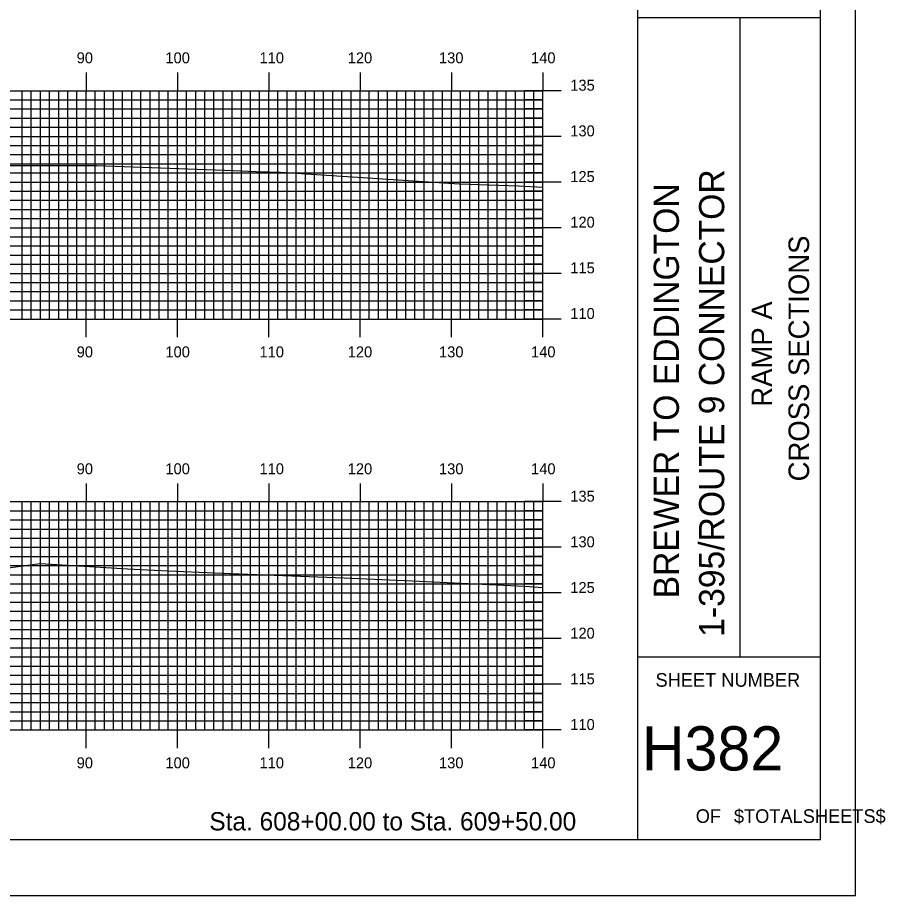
# Model space of a CAD drawing. Extents: x 842962 to 843305, y 363538 to 363758.
# Drawn here: x 843210.4 to 843305.4, y 363537.6 to 363633.7 of the extents above; entities that cross this region are included whole.
import ezdxf

# ---------------------------------------------------------------- set-up
doc = ezdxf.new("R2010")
doc.units = 0
for name, color, linetype in [('BORDER', 7, 'Continuous'), ('H_V ANNOTATION', 7, 'Continuous'), ('MAJOR', 7, 'Continuous'), ('MINOR', 7, 'Continuous'), ('PLOT BOUNDARY', 7, 'Continuous'), ('S_Roadway_Centerline', 7, 'Continuous')]:
    doc.layers.add(name, color=color, linetype=linetype)

msp = doc.modelspace()

# ---------------------------------------------------------------- linework, layer by layer
at = {"layer": 'BORDER'}
for p, q in [((843278.311, 363543.721), (843278.311, 363753.721)), ((843278.311, 363633.727), (843298.311, 363633.727)), ((843289.493, 363563.727), (843289.493, 363633.727)), ((843278.311, 363563.727), (843298.311, 363563.727))]:
    msp.add_line(p, q, dxfattribs=at)
msp.add_lwpolyline([(842978.311, 363543.721), (843298.311, 363543.721), (843298.311, 363753.721), (842978.311, 363753.721)], close=True, dxfattribs=at)
at = {"layer": 'MAJOR'}
for p, q in [((843217.911, 363627.725), (843217.911, 363625.721)), ((843227.911, 363627.725), (843227.911, 363625.721)), ((843237.911, 363627.725), (843237.911, 363625.721)), ((843247.911, 363627.725), (843247.911, 363625.721)), ((843257.911, 363627.725), (843257.911, 363625.721)), ((843267.911, 363627.725), (843267.911, 363625.721)), ((842987.911, 363625.721), (843267.911, 363625.721)), ((842987.911, 363625.721), (843267.911, 363625.721)), ((843217.911, 363600.721), (843217.911, 363625.721)), ((843227.911, 363600.721), (843227.911, 363625.721)), ((843237.911, 363600.721), (843237.911, 363625.721)), ((843247.911, 363600.721), (843247.911, 363625.721)), ((843257.911, 363600.721), (843257.911, 363625.721)), ((843269.915, 363625.721), (843265.907, 363625.721)), ((843267.911, 363600.721), (843267.911, 363625.721)), ((843267.911, 363600.721), (843267.911, 363625.721)), ((842987.911, 363620.721), (843267.911, 363620.721)), ((843269.915, 363620.721), (843265.907, 363620.721)), ((842987.911, 363615.721), (843267.911, 363615.721)), ((843269.915, 363615.721), (843265.907, 363615.721)), ((842987.911, 363610.721), (843267.911, 363610.721)), ((843269.915, 363610.721), (843265.907, 363610.721)), ((842987.911, 363605.721), (843267.911, 363605.721)), ((843269.915, 363605.721), (843265.907, 363605.721)), ((842987.911, 363600.721), (843267.911, 363600.721)), ((842987.911, 363600.721), (843267.911, 363600.721)), ((843217.911, 363598.717), (843217.911, 363600.721)), ((843227.911, 363598.717), (843227.911, 363600.721)), ((843237.911, 363598.717), (843237.911, 363600.721)), ((843247.911, 363598.717), (843247.911, 363600.721)), ((843257.911, 363598.717), (843257.911, 363600.721)), ((843269.915, 363600.721), (843265.907, 363600.721)), ((843267.911, 363598.717), (843267.911, 363600.721)), ((843217.911, 363582.725), (843217.911, 363580.721)), ((843227.911, 363582.725), (843227.911, 363580.721)), ((843237.911, 363582.725), (843237.911, 363580.721)), ((843247.911, 363582.725), (843247.911, 363580.721)), ((843257.911, 363582.725), (843257.911, 363580.721)), ((843267.911, 363582.725), (843267.911, 363580.721)), ((842987.911, 363580.721), (843267.911, 363580.721)), ((842987.911, 363580.721), (843267.911, 363580.721)), ((843217.911, 363555.721), (843217.911, 363580.721)), ((843227.911, 363555.721), (843227.911, 363580.721)), ((843237.911, 363555.721), (843237.911, 363580.721)), ((843247.911, 363555.721), (843247.911, 363580.721)), ((843257.911, 363555.721), (843257.911, 363580.721)), ((843269.915, 363580.721), (843265.907, 363580.721)), ((843267.911, 363555.721), (843267.911, 363580.721)), ((843267.911, 363555.721), (843267.911, 363580.721)), ((842987.911, 363575.721), (843267.911, 363575.721)), ((843269.915, 363575.721), (843265.907, 363575.721)), ((842987.911, 363570.721), (843267.911, 363570.721)), ((843269.915, 363570.721), (843265.907, 363570.721)), ((842987.911, 363565.721), (843267.911, 363565.721)), ((843269.915, 363565.721), (843265.907, 363565.721)), ((842987.911, 363560.721), (843267.911, 363560.721)), ((843269.915, 363560.721), (843265.907, 363560.721)), ((842987.911, 363555.721), (843267.911, 363555.721)), ((842987.911, 363555.721), (843267.911, 363555.721)), ((843217.911, 363553.717), (843217.911, 363555.721)), ((843227.911, 363553.717), (843227.911, 363555.721)), ((843237.911, 363553.717), (843237.911, 363555.721)), ((843247.911, 363553.717), (843247.911, 363555.721)), ((843257.911, 363553.717), (843257.911, 363555.721)), ((843269.915, 363555.721), (843265.907, 363555.721)), ((843267.911, 363553.717), (843267.911, 363555.721))]:
    msp.add_line(p, q, dxfattribs=at)
at = {"layer": 'MINOR'}
for p, q in [((843210.911, 363600.721), (843210.911, 363625.721)), ((843211.911, 363600.721), (843211.911, 363625.721)), ((843212.911, 363600.721), (843212.911, 363625.721)), ((843213.911, 363600.721), (843213.911, 363625.721)), ((843214.911, 363600.721), (843214.911, 363625.721)), ((843215.911, 363600.721), (843215.911, 363625.721)), ((843216.911, 363600.721), (843216.911, 363625.721)), ((843218.911, 363600.721), (843218.911, 363625.721)), ((843219.911, 363600.721), (843219.911, 363625.721)), ((843220.911, 363600.721), (843220.911, 363625.721)), ((843221.911, 363600.721), (843221.911, 363625.721)), ((843222.911, 363600.721), (843222.911, 363625.721)), ((843223.911, 363600.721), (843223.911, 363625.721)), ((843224.911, 363600.721), (843224.911, 363625.721)), ((843225.911, 363600.721), (843225.911, 363625.721)), ((843226.911, 363600.721), (843226.911, 363625.721)), ((843228.911, 363600.721), (843228.911, 363625.721)), ((843229.911, 363600.721), (843229.911, 363625.721)), ((843230.911, 363600.721), (843230.911, 363625.721)), ((843231.911, 363600.721), (843231.911, 363625.721)), ((843232.911, 363600.721), (843232.911, 363625.721)), ((843233.911, 363600.721), (843233.911, 363625.721)), ((843234.911, 363600.721), (843234.911, 363625.721)), ((843235.911, 363600.721), (843235.911, 363625.721)), ((843236.911, 363600.721), (843236.911, 363625.721)), ((843238.911, 363600.721), (843238.911, 363625.721)), ((843239.911, 363600.721), (843239.911, 363625.721)), ((843240.911, 363600.721), (843240.911, 363625.721)), ((843241.911, 363600.721), (843241.911, 363625.721)), ((843242.911, 363600.721), (843242.911, 363625.721)), ((843243.911, 363600.721), (843243.911, 363625.721)), ((843244.911, 363600.721), (843244.911, 363625.721)), ((843245.911, 363600.721), (843245.911, 363625.721)), ((843246.911, 363600.721), (843246.911, 363625.721)), ((843248.911, 363600.721), (843248.911, 363625.721)), ((843249.911, 363600.721), (843249.911, 363625.721)), ((843250.911, 363600.721), (843250.911, 363625.721)), ((843251.911, 363600.721), (843251.911, 363625.721)), ((843252.911, 363600.721), (843252.911, 363625.721)), ((843253.911, 363600.721), (843253.911, 363625.721)), ((843254.911, 363600.721), (843254.911, 363625.721)), ((843255.911, 363600.721), (843255.911, 363625.721)), ((843256.911, 363600.721), (843256.911, 363625.721)), ((843258.911, 363600.721), (843258.911, 363625.721)), ((843259.911, 363600.721), (843259.911, 363625.721)), ((843260.911, 363600.721), (843260.911, 363625.721)), ((843261.911, 363600.721), (843261.911, 363625.721)), ((843262.911, 363600.721), (843262.911, 363625.721)), ((843263.911, 363600.721), (843263.911, 363625.721)), ((843264.911, 363600.721), (843264.911, 363625.721)), ((843265.911, 363600.721), (843265.911, 363625.721)), ((843266.911, 363600.721), (843266.911, 363625.721)), ((842987.911, 363624.721), (843267.911, 363624.721)), ((843267.911, 363624.721), (843265.907, 363624.721)), ((842987.911, 363623.721), (843267.911, 363623.721)), ((843267.911, 363623.721), (843265.907, 363623.721)), ((842987.911, 363622.721), (843267.911, 363622.721)), ((843267.911, 363622.721), (843265.907, 363622.721)), ((842987.911, 363621.721), (843267.911, 363621.721)), ((843267.911, 363621.721), (843265.907, 363621.721)), ((842987.911, 363619.721), (843267.911, 363619.721)), ((843267.911, 363619.721), (843265.907, 363619.721)), ((842987.911, 363618.721), (843267.911, 363618.721)), ((843267.911, 363618.721), (843265.907, 363618.721)), ((842987.911, 363617.721), (843267.911, 363617.721)), ((843267.911, 363617.721), (843265.907, 363617.721)), ((842987.911, 363616.721), (843267.911, 363616.721)), ((843267.911, 363616.721), (843265.907, 363616.721)), ((842987.911, 363614.721), (843267.911, 363614.721)), ((843267.911, 363614.721), (843265.907, 363614.721)), ((842987.911, 363613.721), (843267.911, 363613.721)), ((843267.911, 363613.721), (843265.907, 363613.721)), ((842987.911, 363612.721), (843267.911, 363612.721)), ((843267.911, 363612.721), (843265.907, 363612.721)), ((842987.911, 363611.721), (843267.911, 363611.721)), ((843267.911, 363611.721), (843265.907, 363611.721)), ((842987.911, 363609.721), (843267.911, 363609.721)), ((843267.911, 363609.721), (843265.907, 363609.721)), ((842987.911, 363608.721), (843267.911, 363608.721)), ((843267.911, 363608.721), (843265.907, 363608.721)), ((842987.911, 363607.721), (843267.911, 363607.721)), ((843267.911, 363607.721), (843265.907, 363607.721)), ((842987.911, 363606.721), (843267.911, 363606.721)), ((843267.911, 363606.721), (843265.907, 363606.721)), ((842987.911, 363604.721), (843267.911, 363604.721)), ((843267.911, 363604.721), (843265.907, 363604.721)), ((842987.911, 363603.721), (843267.911, 363603.721)), ((843267.911, 363603.721), (843265.907, 363603.721)), ((842987.911, 363602.721), (843267.911, 363602.721)), ((843267.911, 363602.721), (843265.907, 363602.721)), ((842987.911, 363601.721), (843267.911, 363601.721)), ((843267.911, 363601.721), (843265.907, 363601.721)), ((843210.911, 363555.721), (843210.911, 363580.721)), ((843211.911, 363555.721), (843211.911, 363580.721)), ((843212.911, 363555.721), (843212.911, 363580.721)), ((843213.911, 363555.721), (843213.911, 363580.721)), ((843214.911, 363555.721), (843214.911, 363580.721)), ((843215.911, 363555.721), (843215.911, 363580.721)), ((843216.911, 363555.721), (843216.911, 363580.721)), ((843218.911, 363555.721), (843218.911, 363580.721)), ((843219.911, 363555.721), (843219.911, 363580.721)), ((843220.911, 363555.721), (843220.911, 363580.721)), ((843221.911, 363555.721), (843221.911, 363580.721)), ((843222.911, 363555.721), (843222.911, 363580.721)), ((843223.911, 363555.721), (843223.911, 363580.721)), ((843224.911, 363555.721), (843224.911, 363580.721)), ((843225.911, 363555.721), (843225.911, 363580.721)), ((843226.911, 363555.721), (843226.911, 363580.721)), ((843228.911, 363555.721), (843228.911, 363580.721)), ((843229.911, 363555.721), (843229.911, 363580.721)), ((843230.911, 363555.721), (843230.911, 363580.721)), ((843231.911, 363555.721), (843231.911, 363580.721)), ((843232.911, 363555.721), (843232.911, 363580.721)), ((843233.911, 363555.721), (843233.911, 363580.721)), ((843234.911, 363555.721), (843234.911, 363580.721)), ((843235.911, 363555.721), (843235.911, 363580.721)), ((843236.911, 363555.721), (843236.911, 363580.721)), ((843238.911, 363555.721), (843238.911, 363580.721)), ((843239.911, 363555.721), (843239.911, 363580.721)), ((843240.911, 363555.721), (843240.911, 363580.721)), ((843241.911, 363555.721), (843241.911, 363580.721)), ((843242.911, 363555.721), (843242.911, 363580.721)), ((843243.911, 363555.721), (843243.911, 363580.721)), ((843244.911, 363555.721), (843244.911, 363580.721)), ((843245.911, 363555.721), (843245.911, 363580.721)), ((843246.911, 363555.721), (843246.911, 363580.721)), ((843248.911, 363555.721), (843248.911, 363580.721)), ((843249.911, 363555.721), (843249.911, 363580.721)), ((843250.911, 363555.721), (843250.911, 363580.721)), ((843251.911, 363555.721), (843251.911, 363580.721)), ((843252.911, 363555.721), (843252.911, 363580.721)), ((843253.911, 363555.721), (843253.911, 363580.721)), ((843254.911, 363555.721), (843254.911, 363580.721)), ((843255.911, 363555.721), (843255.911, 363580.721)), ((843256.911, 363555.721), (843256.911, 363580.721)), ((843258.911, 363555.721), (843258.911, 363580.721)), ((843259.911, 363555.721), (843259.911, 363580.721)), ((843260.911, 363555.721), (843260.911, 363580.721)), ((843261.911, 363555.721), (843261.911, 363580.721)), ((843262.911, 363555.721), (843262.911, 363580.721)), ((843263.911, 363555.721), (843263.911, 363580.721)), ((843264.911, 363555.721), (843264.911, 363580.721)), ((843265.911, 363555.721), (843265.911, 363580.721)), ((843266.911, 363555.721), (843266.911, 363580.721)), ((842987.911, 363579.721), (843267.911, 363579.721)), ((843267.911, 363579.721), (843265.907, 363579.721)), ((842987.911, 363578.721), (843267.911, 363578.721)), ((843267.911, 363578.721), (843265.907, 363578.721)), ((842987.911, 363577.721), (843267.911, 363577.721)), ((843267.911, 363577.721), (843265.907, 363577.721)), ((842987.911, 363576.721), (843267.911, 363576.721)), ((843267.911, 363576.721), (843265.907, 363576.721)), ((842987.911, 363574.721), (843267.911, 363574.721)), ((843267.911, 363574.721), (843265.907, 363574.721)), ((842987.911, 363573.721), (843267.911, 363573.721)), ((843267.911, 363573.721), (843265.907, 363573.721)), ((842987.911, 363572.721), (843267.911, 363572.721)), ((843267.911, 363572.721), (843265.907, 363572.721)), ((842987.911, 363571.721), (843267.911, 363571.721)), ((843267.911, 363571.721), (843265.907, 363571.721)), ((842987.911, 363569.721), (843267.911, 363569.721)), ((843267.911, 363569.721), (843265.907, 363569.721)), ((842987.911, 363568.721), (843267.911, 363568.721)), ((843267.911, 363568.721), (843265.907, 363568.721)), ((842987.911, 363567.721), (843267.911, 363567.721)), ((843267.911, 363567.721), (843265.907, 363567.721)), ((842987.911, 363566.721), (843267.911, 363566.721)), ((843267.911, 363566.721), (843265.907, 363566.721)), ((842987.911, 363564.721), (843267.911, 363564.721)), ((843267.911, 363564.721), (843265.907, 363564.721)), ((842987.911, 363563.721), (843267.911, 363563.721)), ((843267.911, 363563.721), (843265.907, 363563.721)), ((842987.911, 363562.721), (843267.911, 363562.721)), ((843267.911, 363562.721), (843265.907, 363562.721)), ((842987.911, 363561.721), (843267.911, 363561.721)), ((843267.911, 363561.721), (843265.907, 363561.721)), ((842987.911, 363559.721), (843267.911, 363559.721)), ((843267.911, 363559.721), (843265.907, 363559.721)), ((842987.911, 363558.721), (843267.911, 363558.721)), ((843267.911, 363558.721), (843265.907, 363558.721)), ((842987.911, 363557.721), (843267.911, 363557.721)), ((843267.911, 363557.721), (843265.907, 363557.721)), ((842987.911, 363556.721), (843267.911, 363556.721)), ((843267.911, 363556.721), (843265.907, 363556.721))]:
    msp.add_line(p, q, dxfattribs=at)
at = {"layer": 'PLOT BOUNDARY'}
msp.add_lwpolyline([(842962.124, 363537.603), (843302.124, 363537.603), (843302.124, 363757.603), (842962.124, 363757.603)], close=True, dxfattribs=at)
at = {"layer": 'S_Roadway_Centerline'}
for points in [[(843207.25, 363617.544), (843219.101, 363617.532), (843234.056, 363616.987), (843236.536, 363616.889), (843239.2, 363616.797), (843248.158, 363616.2), (843258.741, 363615.523), (843265.229, 363615.302), (843267.911, 363615.173)], [(843207.214, 363573.172), (843212.898, 363573.941), (843222.493, 363573.381), (843225.346, 363573.207), (843226.845, 363573.148), (843233.732, 363572.854), (843246.169, 363572.384), (843253.587, 363572.048), (843265.912, 363571.452), (843267.911, 363571.325)]]:
    msp.add_lwpolyline(points, dxfattribs=at)

# ---------------------------------------------------------------- texts
at = {"layer": 'BORDER'}
for s, height, p in [('1-395/ROUTE 9 CONNECTOR', 2.75575, (843287.76, 363565.921)), ('BREWER TO EDDINGTON', 2.75575, (843282.8, 363570.13)), ('CROSS SECTIONS', 2.25, (843297.052, 363582.943)), ('RAMP A', 2.25, (843293.002, 363591.118))]:
    msp.add_text(s, height=height, rotation=90, dxfattribs=at).set_placement(p)
for s, height, p in [('SHEET NUMBER', 1.49054, (843280.242, 363560.454)), ('H382', 4.8388, (843278.751, 363551.286)), ('OF', 1.4905, (843284.645, 363545.547)), ('$TOTALSHEETS$', 1.49054, (843288.824, 363545.547))]:
    msp.add_text(s, height=height, dxfattribs=at).set_placement(p)
at = {"layer": 'H_V ANNOTATION'}
for s, height, p in [('90', 1.2, (843216.883, 363628.721)), ('100', 1.2, (843226.595, 363628.721)), ('110', 1.2, (843236.894, 363628.721)), ('120', 1.2, (843246.552, 363628.721)), ('130', 1.2, (843256.541, 363628.721)), ('140', 1.2, (843266.616, 363628.721)), ('135', 1.2, (843270.911, 363625.721)), ('130', 1.2, (843270.911, 363620.721)), ('125', 1.2, (843270.911, 363615.721)), ('120', 1.2, (843270.911, 363610.721)), ('115', 1.2, (843270.911, 363605.721)), ('110', 1.2, (843270.911, 363600.721)), ('90', 1.2, (843216.883, 363596.521)), ('100', 1.2, (843226.595, 363596.521)), ('110', 1.2, (843236.894, 363596.521)), ('120', 1.2, (843246.552, 363596.521)), ('130', 1.2, (843256.541, 363596.521)), ('140', 1.2, (843266.616, 363596.521)), ('90', 1.2, (843216.883, 363583.721)), ('100', 1.2, (843226.595, 363583.721)), ('110', 1.2, (843236.894, 363583.721)), ('120', 1.2, (843246.552, 363583.721)), ('130', 1.2, (843256.541, 363583.721)), ('140', 1.2, (843266.616, 363583.721)), ('135', 1.2, (843270.911, 363580.721)), ('130', 1.2, (843270.911, 363575.721)), ('125', 1.2, (843270.911, 363570.721)), ('120', 1.2, (843270.911, 363565.721)), ('115', 1.2, (843270.911, 363560.721)), ('110', 1.2, (843270.911, 363555.721)), ('90', 1.2, (843216.883, 363551.521)), ('100', 1.2, (843226.595, 363551.521)), ('110', 1.2, (843236.894, 363551.521)), ('120', 1.2, (843246.552, 363551.521)), ('130', 1.2, (843256.541, 363551.521)), ('140', 1.2, (843266.616, 363551.521)), ('Sta. 608+00.00 to Sta. 609+50.00', 2.0004, (843231.403, 363544.721))]:
    msp.add_text(s, height=height, dxfattribs=at).set_placement(p)

doc.saveas('drawing.dxf')
